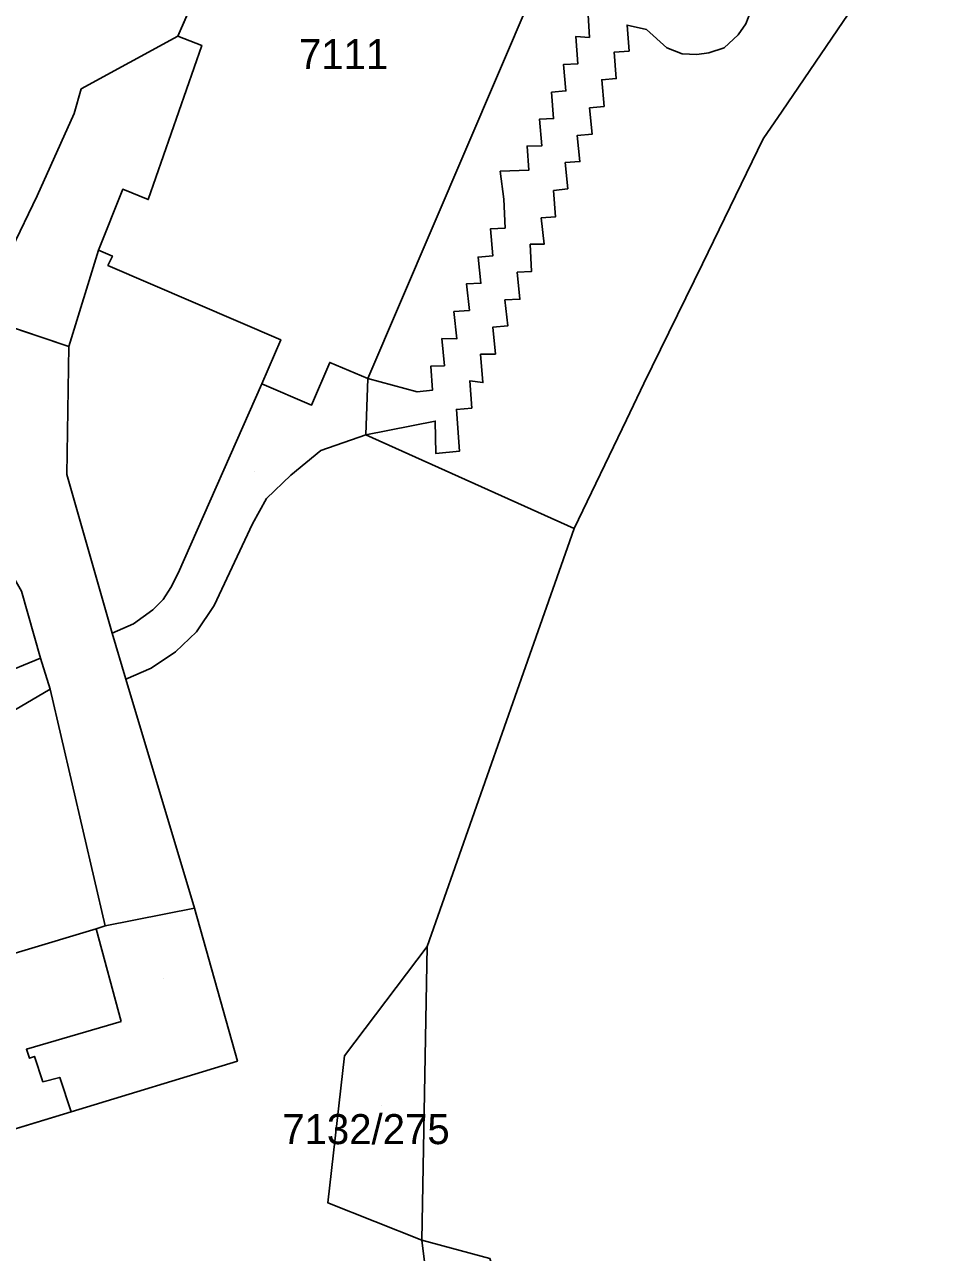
# Model space of a CAD drawing. Extents: x -266199 to -261993, y -1239047 to -1235108.
# Drawn here: x -263424.4 to -263363.8, y -1236263.2 to -1236181.4 of the extents above; entities that cross this region are included whole.
import ezdxf

# ---------------------------------------------------------------- set-up
doc = ezdxf.new("R2010")
doc.units = 0
for name, color, linetype in [('body_kn', 7, 'Continuous'), ('kladpar_druhypozemkov', 7, 'Continuous'), ('kladpar_hranice', 7, 'Continuous'), ('kladpar_parcelnecisla', 7, 'Continuous'), ('kladpar_plochy', 7, 'Continuous'), ('zappar_hrandruhpozemk', 7, 'Continuous'), ('zuob_linie', 7, 'Continuous'), ('zuob_plochy', 7, 'Continuous')]:
    doc.layers.add(name, color=color, linetype=linetype)

msp = doc.modelspace()

# ---------------------------------------------------------------- linework, layer by layer
at = {"layer": 'body_kn'}
for p, q in [((-263384.27, -1236181.46), (-263384.27, -1236181.46)), ((-263414.19, -1236182.19), (-263414.19, -1236182.19)), ((-263414.19, -1236182.19), (-263414.19, -1236182.19)), ((-263387.67, -1236182.21), (-263387.67, -1236182.21)), ((-263386.77, -1236182.28), (-263386.77, -1236182.28)), ((-263382.98, -1236181.76), (-263382.98, -1236181.76)), ((-263376.87, -1236182.1), (-263376.87, -1236182.1)), ((-263412.6, -1236182.81), (-263412.6, -1236182.81)), ((-263381.61, -1236182.96), (-263381.61, -1236182.96)), ((-263377.79, -1236182.98), (-263377.79, -1236182.98)), ((-263385.13, -1236183.26), (-263385.13, -1236183.26)), ((-263384.13, -1236183.19), (-263384.13, -1236183.19)), ((-263380.6, -1236183.36), (-263380.6, -1236183.36)), ((-263379.63, -1236183.42), (-263379.63, -1236183.42)), ((-263378.83, -1236183.31), (-263378.83, -1236183.31)), ((-263388.5, -1236184.08), (-263388.5, -1236184.08)), ((-263387.55, -1236184.04), (-263387.55, -1236184.04)), ((-263385.95, -1236185.1), (-263385.95, -1236185.1)), ((-263384.99, -1236185.02), (-263384.99, -1236185.02)), ((-263420.64, -1236185.71), (-263420.64, -1236185.71)), ((-263389.29, -1236185.93), (-263389.29, -1236185.93)), ((-263388.34, -1236185.84), (-263388.34, -1236185.84)), ((-263386.76, -1236186.97), (-263386.76, -1236186.97)), ((-263385.8, -1236186.87), (-263385.8, -1236186.87)), ((-263373.94, -1236187.19), (-263373.94, -1236187.19)), ((-263421.09, -1236187.35), (-263421.09, -1236187.35)), ((-263390.11, -1236187.73), (-263390.11, -1236187.73)), ((-263389.16, -1236187.68), (-263389.16, -1236187.68)), ((-263387.58, -1236188.81), (-263387.58, -1236188.81)), ((-263386.6, -1236188.73), (-263386.6, -1236188.73)), ((-263390.93, -1236189.52), (-263390.93, -1236189.52)), ((-263389.94, -1236189.49), (-263389.94, -1236189.49)), ((-263375.19, -1236189.03), (-263375.19, -1236189.03)), ((-263392.73, -1236191.19), (-263392.73, -1236191.19)), ((-263390.81, -1236191.11), (-263390.81, -1236191.11)), ((-263388.39, -1236190.62), (-263388.39, -1236190.62)), ((-263387.41, -1236190.55), (-263387.41, -1236190.55)), ((-263423.56, -1236192.84), (-263423.56, -1236192.84)), ((-263417.86, -1236192.39), (-263417.86, -1236192.39)), ((-263389.16, -1236192.48), (-263389.16, -1236192.48)), ((-263388.22, -1236192.36), (-263388.22, -1236192.36)), ((-263416.17, -1236193.08), (-263416.17, -1236193.08)), ((-263392.47, -1236193.06), (-263392.47, -1236193.06)), ((-263389.98, -1236194.3), (-263389.98, -1236194.3)), ((-263389.03, -1236194.22), (-263389.03, -1236194.22)), ((-263393.36, -1236195.02), (-263393.36, -1236195.02)), ((-263392.39, -1236194.98), (-263392.39, -1236194.98)), ((-263390.72, -1236196.06), (-263390.72, -1236196.06)), ((-263389.78, -1236196.05), (-263389.78, -1236196.05)), ((-263419.48, -1236196.44), (-263419.48, -1236196.44)), ((-263418.55, -1236196.84), (-263418.55, -1236196.84)), ((-263394.19, -1236196.91), (-263394.19, -1236196.91)), ((-263393.21, -1236196.83), (-263393.21, -1236196.83)), ((-263418.85, -1236197.47), (-263418.85, -1236197.47)), ((-263390.63, -1236197.87), (-263390.63, -1236197.87)), ((-263379.25, -1236197.36), (-263379.25, -1236197.36)), ((-263394.96, -1236198.69), (-263394.96, -1236198.69)), ((-263394, -1236198.65), (-263394, -1236198.65)), ((-263391.58, -1236197.92), (-263391.58, -1236197.92)), ((-263392.4, -1236199.76), (-263392.4, -1236199.76)), ((-263391.4, -1236199.72), (-263391.4, -1236199.72)), ((-263395.8, -1236200.54), (-263395.8, -1236200.54)), ((-263394.77, -1236200.46), (-263394.77, -1236200.46)), ((-263393.2, -1236201.58), (-263393.2, -1236201.58)), ((-263392.21, -1236201.5), (-263392.21, -1236201.5)), ((-263407.34, -1236202.42), (-263407.34, -1236202.42)), ((-263396.6, -1236202.34), (-263396.6, -1236202.34)), ((-263395.61, -1236202.36), (-263395.61, -1236202.36)), ((-263421.46, -1236202.87), (-263421.46, -1236202.87)), ((-263421.46, -1236202.87), (-263421.46, -1236202.87)), ((-263394.02, -1236203.38), (-263394.02, -1236203.38)), ((-263393.04, -1236203.37), (-263393.04, -1236203.37)), ((-263404.07, -1236203.93), (-263404.07, -1236203.93)), ((-263397.34, -1236204.19), (-263397.34, -1236204.19)), ((-263396.44, -1236204.15), (-263396.44, -1236204.15)), ((-263401.54, -1236205.01), (-263401.54, -1236205.01)), ((-263401.54, -1236205.01), (-263401.54, -1236205.01)), ((-263394.74, -1236205.15), (-263394.74, -1236205.15)), ((-263408.6, -1236205.36), (-263408.6, -1236205.36)), ((-263408.6, -1236205.36), (-263408.6, -1236205.36)), ((-263398.25, -1236205.88), (-263398.25, -1236205.88)), ((-263397.23, -1236205.78), (-263397.23, -1236205.78)), ((-263393.87, -1236205.27), (-263393.87, -1236205.27)), ((-263383.14, -1236205.34), (-263383.14, -1236205.34)), ((-263405.29, -1236206.78), (-263405.29, -1236206.78)), ((-263395.64, -1236207.06), (-263395.64, -1236207.06)), ((-263394.61, -1236206.97), (-263394.61, -1236206.97)), ((-263397.05, -1236207.84), (-263397.05, -1236207.84)), ((-263384.3, -1236207.75), (-263384.3, -1236207.75)), ((-263401.68, -1236208.75), (-263401.68, -1236208.75)), ((-263404.66, -1236209.79), (-263404.66, -1236209.79)), ((-263397, -1236210), (-263397, -1236210)), ((-263395.44, -1236209.85), (-263395.44, -1236209.85)), ((-263421.59, -1236211.39), (-263421.59, -1236211.39)), ((-263406.67, -1236211.45), (-263406.67, -1236211.45)), ((-263408.28, -1236213), (-263408.28, -1236213)), ((-263409.22, -1236214.69), (-263409.22, -1236214.69)), ((-263387.78, -1236215), (-263387.78, -1236215)), ((-263388.23, -1236216.27), (-263388.23, -1236216.27)), ((-263414.17, -1236217.96), (-263414.17, -1236217.96)), ((-263414.65, -1236218.92), (-263414.65, -1236218.92)), ((-263415.18, -1236219.73), (-263415.18, -1236219.73)), ((-263415.87, -1236220.42), (-263415.87, -1236220.42)), ((-263411.77, -1236220.13), (-263411.77, -1236220.13)), ((-263417.14, -1236221.35), (-263417.14, -1236221.35)), ((-263418.56, -1236221.97), (-263418.56, -1236221.97)), ((-263412.94, -1236221.87), (-263412.94, -1236221.87)), ((-263414.35, -1236223.22), (-263414.35, -1236223.22)), ((-263423.35, -1236223.63), (-263423.35, -1236223.63)), ((-263423.35, -1236223.63), (-263423.35, -1236223.63)), ((-263415.97, -1236224.31), (-263415.97, -1236224.31)), ((-263422.7, -1236225.69), (-263422.7, -1236225.69)), ((-263422.7, -1236225.69), (-263422.7, -1236225.69)), ((-263417.65, -1236225.03), (-263417.65, -1236225.03)), ((-263417.65, -1236225.03), (-263417.65, -1236225.03)), ((-263391.58, -1236225.78), (-263391.58, -1236225.78)), ((-263413.09, -1236240.29), (-263413.09, -1236240.29)), ((-263419.63, -1236241.67), (-263419.63, -1236241.67)), ((-263419.04, -1236241.47), (-263419.04, -1236241.47)), ((-263397.59, -1236242.84), (-263397.59, -1236242.84)), ((-263417.97, -1236247.83), (-263417.97, -1236247.83)), ((-263424.28, -1236249.69), (-263424.28, -1236249.69)), ((-263423.75, -1236250.17), (-263423.75, -1236250.17)), ((-263403.09, -1236250.13), (-263403.09, -1236250.13)), ((-263424.08, -1236250.29), (-263424.08, -1236250.29)), ((-263410.23, -1236250.49), (-263410.23, -1236250.49)), ((-263423.18, -1236251.85), (-263423.18, -1236251.85)), ((-263422.06, -1236251.56), (-263422.06, -1236251.56)), ((-263421.31, -1236253.86), (-263421.31, -1236253.86)), ((-263421.31, -1236253.86), (-263421.31, -1236253.86)), ((-263404.2, -1236259.93), (-263404.2, -1236259.93)), ((-263397.93, -1236262.41), (-263397.93, -1236262.41)), ((-263397.93, -1236262.41), (-263397.93, -1236262.41))]:
    msp.add_line(p, q, dxfattribs=at)
at = {"layer": 'kladpar_druhypozemkov'}
for p, q in [((-263404, -1236181.79), (-263404, -1236181.79)), ((-263409.06, -1236211.18), (-263409.06, -1236211.18)), ((-263415.15, -1236244.95), (-263415.15, -1236244.95)), ((-263400.64, -1236253.42), (-263400.64, -1236253.42))]:
    msp.add_line(p, q, dxfattribs=at)
at = {"layer": 'kladpar_hranice'}
for points in [[(-263367.32, -1236177.43), (-263373.94, -1236187.19), (-263375.19, -1236189.03), (-263379.25, -1236197.36), (-263383.14, -1236205.34), (-263384.3, -1236207.75), (-263387.78, -1236215), (-263401.68, -1236208.75), (-263401.54, -1236205.01), (-263404.07, -1236203.93), (-263405.29, -1236206.78), (-263408.6, -1236205.36), (-263407.34, -1236202.42), (-263418.85, -1236197.47), (-263418.55, -1236196.84), (-263419.48, -1236196.44), (-263417.86, -1236192.39), (-263416.17, -1236193.08), (-263412.6, -1236182.81), (-263414.19, -1236182.19), (-263410.74, -1236174.24)], [(-263410.74, -1236174.24), (-263414.19, -1236182.19), (-263412.6, -1236182.81), (-263416.17, -1236193.08), (-263417.86, -1236192.39), (-263419.48, -1236196.44), (-263418.55, -1236196.84), (-263418.85, -1236197.47), (-263407.34, -1236202.42), (-263408.6, -1236205.36), (-263405.29, -1236206.78), (-263404.07, -1236203.93), (-263401.54, -1236205.01), (-263401.68, -1236208.75), (-263387.78, -1236215), (-263388.23, -1236216.27), (-263391.58, -1236225.78), (-263397.59, -1236242.84), (-263403.09, -1236250.13), (-263404.2, -1236259.93), (-263397.93, -1236262.41), (-263396.48, -1236274.15)], [(-263430.4, -1236194.43), (-263426.52, -1236198.47), (-263427.94, -1236200.69), (-263421.46, -1236202.87), (-263421.59, -1236211.39), (-263418.56, -1236221.97), (-263417.65, -1236225.03), (-263413.09, -1236240.29), (-263419.04, -1236241.47), (-263422.7, -1236225.69), (-263423.35, -1236223.63), (-263424.6, -1236219.17), (-263425.4, -1236217.77), (-263426.52, -1236216.64), (-263427.96, -1236215.86), (-263429.71, -1236215.43), (-263431.06, -1236215.51), (-263432.58, -1236215.9), (-263433.91, -1236216.71), (-263434.97, -1236217.82), (-263458.86, -1236257.26), (-263460.81, -1236262.37), (-263460.72, -1236263.52)], [(-263430.9, -1236256.76), (-263421.31, -1236253.86), (-263410.23, -1236250.49), (-263413.09, -1236240.29), (-263417.65, -1236225.03), (-263418.56, -1236221.97), (-263421.59, -1236211.39), (-263421.46, -1236202.87), (-263427.94, -1236200.69)], [(-263424.6, -1236219.17), (-263423.35, -1236223.63), (-263422.7, -1236225.69), (-263419.04, -1236241.47), (-263419.63, -1236241.67), (-263424.58, -1236243.16)], [(-263440.92, -1236259.8), (-263444.17, -1236249), (-263424.58, -1236243.16), (-263419.63, -1236241.67), (-263419.04, -1236241.47), (-263413.09, -1236240.29), (-263410.23, -1236250.49), (-263421.31, -1236253.86), (-263430.9, -1236256.76), (-263430.43, -1236258.24), (-263432.56, -1236258.89), (-263433.01, -1236257.4), (-263440.92, -1236259.8)], [(-263397.93, -1236262.41), (-263404.2, -1236259.93), (-263403.09, -1236250.13), (-263397.59, -1236242.84), (-263397.93, -1236262.41)], [(-263395.17, -1236279.46), (-263396.48, -1236274.15), (-263397.93, -1236262.41), (-263393.42, -1236263.62), (-263389.22, -1236276.07), (-263389.33, -1236280.76), (-263395.17, -1236279.46)]]:
    msp.add_lwpolyline(points, dxfattribs=at)
at = {"layer": 'kladpar_plochy'}
for p, q in [((-263410.74, -1236174.24), (-263414.19, -1236182.19)), ((-263414.19, -1236182.19), (-263412.6, -1236182.81)), ((-263412.6, -1236182.81), (-263416.17, -1236193.08)), ((-263417.86, -1236192.39), (-263419.48, -1236196.44)), ((-263416.17, -1236193.08), (-263417.86, -1236192.39)), ((-263419.48, -1236196.44), (-263418.55, -1236196.84)), ((-263418.55, -1236196.84), (-263418.85, -1236197.47)), ((-263418.85, -1236197.47), (-263407.34, -1236202.42)), ((-263421.46, -1236202.87), (-263427.94, -1236200.69)), ((-263407.34, -1236202.42), (-263408.6, -1236205.36)), ((-263421.59, -1236211.39), (-263421.46, -1236202.87)), ((-263405.29, -1236206.78), (-263404.07, -1236203.93)), ((-263404.07, -1236203.93), (-263401.54, -1236205.01)), ((-263401.54, -1236205.01), (-263401.68, -1236208.75)), ((-263408.6, -1236205.36), (-263405.29, -1236206.78)), ((-263401.68, -1236208.75), (-263387.78, -1236215)), ((-263418.56, -1236221.97), (-263421.59, -1236211.39)), ((-263387.78, -1236215), (-263388.23, -1236216.27)), ((-263388.23, -1236216.27), (-263391.58, -1236225.78)), ((-263424.6, -1236219.17), (-263423.35, -1236223.63)), ((-263417.65, -1236225.03), (-263418.56, -1236221.97)), ((-263423.35, -1236223.63), (-263422.7, -1236225.69)), ((-263422.7, -1236225.69), (-263419.04, -1236241.47)), ((-263413.09, -1236240.29), (-263417.65, -1236225.03)), ((-263391.58, -1236225.78), (-263397.59, -1236242.84)), ((-263410.23, -1236250.49), (-263413.09, -1236240.29)), ((-263419.63, -1236241.67), (-263424.58, -1236243.16)), ((-263419.04, -1236241.47), (-263419.63, -1236241.67)), ((-263397.59, -1236242.84), (-263403.09, -1236250.13)), ((-263403.09, -1236250.13), (-263404.2, -1236259.93)), ((-263421.31, -1236253.86), (-263410.23, -1236250.49)), ((-263430.9, -1236256.76), (-263421.31, -1236253.86)), ((-263404.2, -1236259.93), (-263397.93, -1236262.41)), ((-263397.93, -1236262.41), (-263396.48, -1236274.15))]:
    msp.add_line(p, q, dxfattribs=at)
for points in [[(-263367.32, -1236177.43), (-263373.94, -1236187.19), (-263375.19, -1236189.03), (-263379.25, -1236197.36), (-263383.14, -1236205.34), (-263384.3, -1236207.75), (-263387.78, -1236215), (-263401.68, -1236208.75), (-263401.54, -1236205.01), (-263404.07, -1236203.93), (-263405.29, -1236206.78), (-263408.6, -1236205.36), (-263407.34, -1236202.42), (-263418.85, -1236197.47), (-263418.55, -1236196.84), (-263419.48, -1236196.44), (-263417.86, -1236192.39), (-263416.17, -1236193.08), (-263412.6, -1236182.81), (-263414.19, -1236182.19), (-263410.74, -1236174.24)], [(-263427.94, -1236200.69), (-263421.46, -1236202.87), (-263421.59, -1236211.39), (-263418.56, -1236221.97), (-263417.65, -1236225.03), (-263413.09, -1236240.29), (-263419.04, -1236241.47), (-263422.7, -1236225.69), (-263423.35, -1236223.63), (-263424.6, -1236219.17)]]:
    msp.add_lwpolyline(points, dxfattribs=at)
for points in [[(-263440.92, -1236259.8), (-263444.17, -1236249), (-263424.58, -1236243.16), (-263419.63, -1236241.67), (-263419.04, -1236241.47), (-263413.09, -1236240.29), (-263410.23, -1236250.49), (-263421.31, -1236253.86), (-263430.9, -1236256.76), (-263430.43, -1236258.24), (-263432.56, -1236258.89), (-263433.01, -1236257.4)], [(-263397.93, -1236262.41), (-263404.2, -1236259.93), (-263403.09, -1236250.13), (-263397.59, -1236242.84)], [(-263395.17, -1236279.46), (-263396.48, -1236274.15), (-263397.93, -1236262.41), (-263393.42, -1236263.62), (-263389.22, -1236276.07), (-263389.33, -1236280.76)]]:
    msp.add_lwpolyline(points, close=True, dxfattribs=at)
at = {"layer": 'zappar_hrandruhpozemk'}
for p, q in [((-263386.23, -1236169.24), (-263401.54, -1236205.01)), ((-263376.87, -1236182.1), (-263377.79, -1236182.98)), ((-263421.09, -1236187.35), (-263423.56, -1236192.84)), ((-263392.47, -1236193.06), (-263392.73, -1236191.19)), ((-263421.46, -1236202.87), (-263419.48, -1236196.44)), ((-263408.6, -1236205.36), (-263414.17, -1236217.96)), ((-263411.77, -1236220.13), (-263409.22, -1236214.69)), ((-263423.35, -1236223.63), (-263428.01, -1236225.54)), ((-263417.97, -1236247.83), (-263419.63, -1236241.67))]:
    msp.add_line(p, q, dxfattribs=at)
for points in [[(-263386.29, -1236173.72), (-263384.57, -1236174.46), (-263385.53, -1236176.73), (-263383.03, -1236177.82), (-263382.44, -1236177.01), (-263381.82, -1236176.45), (-263381, -1236176.04), (-263380.03, -1236175.96), (-263379.14, -1236176.12), (-263378.33, -1236176.35), (-263377.52, -1236176.83), (-263376.83, -1236177.46), (-263376.34, -1236178.17), (-263376.06, -1236179), (-263375.97, -1236179.69), (-263376.05, -1236180.57), (-263376.36, -1236181.38), (-263376.87, -1236182.1)], [(-263392.73, -1236191.19), (-263390.81, -1236191.11), (-263390.93, -1236189.52), (-263389.94, -1236189.49), (-263390.11, -1236187.73), (-263389.16, -1236187.68), (-263389.29, -1236185.93), (-263388.34, -1236185.84), (-263388.5, -1236184.08), (-263387.55, -1236184.04), (-263387.67, -1236182.21), (-263386.77, -1236182.28), (-263386.87, -1236180.4), (-263385.96, -1236180.38), (-263385.54, -1236179), (-263387.95, -1236177.88)], [(-263377.79, -1236182.98), (-263378.83, -1236183.31), (-263379.63, -1236183.42), (-263380.6, -1236183.36), (-263381.61, -1236182.96), (-263382.98, -1236181.76), (-263384.27, -1236181.46), (-263384.13, -1236183.19), (-263385.13, -1236183.26), (-263384.99, -1236185.02), (-263385.95, -1236185.1), (-263385.8, -1236186.87), (-263386.76, -1236186.97), (-263386.6, -1236188.73), (-263387.58, -1236188.81), (-263387.41, -1236190.55), (-263388.39, -1236190.62), (-263388.22, -1236192.36), (-263389.16, -1236192.48), (-263389.03, -1236194.22), (-263389.98, -1236194.3), (-263389.78, -1236196.05), (-263390.72, -1236196.06), (-263390.63, -1236197.87), (-263391.58, -1236197.92), (-263391.4, -1236199.72), (-263392.4, -1236199.76), (-263392.21, -1236201.5), (-263393.2, -1236201.58), (-263393.04, -1236203.37), (-263394.02, -1236203.38), (-263393.87, -1236205.27), (-263394.74, -1236205.15), (-263394.61, -1236206.97), (-263395.64, -1236207.06), (-263395.44, -1236209.85), (-263397, -1236210), (-263397.05, -1236207.84), (-263401.68, -1236208.75)], [(-263414.19, -1236182.19), (-263420.64, -1236185.71), (-263421.09, -1236187.35)], [(-263423.56, -1236192.84), (-263425.27, -1236196.38), (-263426.52, -1236198.47)], [(-263401.54, -1236205.01), (-263398.25, -1236205.88), (-263397.23, -1236205.78), (-263397.34, -1236204.19), (-263396.44, -1236204.15), (-263396.6, -1236202.34), (-263395.61, -1236202.36), (-263395.8, -1236200.54), (-263394.77, -1236200.46), (-263394.96, -1236198.69), (-263394, -1236198.65), (-263394.19, -1236196.91), (-263393.21, -1236196.83), (-263393.36, -1236195.02), (-263392.39, -1236194.98), (-263392.47, -1236193.06)], [(-263409.22, -1236214.69), (-263408.28, -1236213), (-263406.67, -1236211.45), (-263404.66, -1236209.79), (-263401.68, -1236208.75)], [(-263414.17, -1236217.96), (-263414.65, -1236218.92), (-263415.18, -1236219.73), (-263415.87, -1236220.42), (-263417.14, -1236221.35), (-263418.56, -1236221.97)], [(-263417.65, -1236225.03), (-263415.97, -1236224.31), (-263414.35, -1236223.22), (-263412.94, -1236221.87), (-263411.77, -1236220.13)], [(-263422.7, -1236225.69), (-263426.23, -1236227.77), (-263430.58, -1236230.35), (-263433.83, -1236232.88), (-263436.43, -1236235.26), (-263438.79, -1236237.6), (-263441.61, -1236241.11), (-263443.98, -1236244.59), (-263444.9, -1236246.35)], [(-263421.31, -1236253.86), (-263422.06, -1236251.56), (-263423.18, -1236251.85), (-263423.75, -1236250.17), (-263424.08, -1236250.29), (-263424.28, -1236249.69), (-263417.97, -1236247.83)]]:
    msp.add_lwpolyline(points, dxfattribs=at)
at = {"layer": 'zuob_linie'}
msp.add_lwpolyline([(-263471.6, -1236129.07), (-263458.94, -1236134.31), (-263442.82, -1236140.99), (-263413.44, -1236152.05), (-263408.66, -1236155.08), (-263383.22, -1236164.89), (-263363.79, -1236172.22), (-263365, -1236174), (-263367.32, -1236177.43), (-263373.94, -1236187.19), (-263375.19, -1236189.03), (-263379.25, -1236197.36), (-263383.14, -1236205.34), (-263384.3, -1236207.75), (-263387.78, -1236215), (-263388.23, -1236216.27), (-263391.58, -1236225.78), (-263397.59, -1236242.84), (-263397.93, -1236262.41), (-263393.42, -1236263.62)], dxfattribs=at)
at = {"layer": 'zuob_plochy'}
msp.add_lwpolyline([(-263471.6, -1236129.07), (-263458.94, -1236134.31), (-263442.82, -1236140.99), (-263413.44, -1236152.05), (-263408.66, -1236155.08), (-263383.22, -1236164.89), (-263363.79, -1236172.22), (-263365, -1236174), (-263367.32, -1236177.43), (-263373.94, -1236187.19), (-263375.19, -1236189.03), (-263379.25, -1236197.36), (-263383.14, -1236205.34), (-263384.3, -1236207.75), (-263387.78, -1236215), (-263388.23, -1236216.27), (-263391.58, -1236225.78), (-263397.59, -1236242.84), (-263397.93, -1236262.41), (-263393.42, -1236263.62)], dxfattribs=at)

# ---------------------------------------------------------------- texts
at = {"layer": 'kladpar_parcelnecisla'}
for s, p in [('7111', (-263406.124, -1236184.39)), ('7132/275', (-263407.239, -1236256.01))]:
    msp.add_text(s, height=2, dxfattribs=at).set_placement(p)

doc.saveas('drawing.dxf')
